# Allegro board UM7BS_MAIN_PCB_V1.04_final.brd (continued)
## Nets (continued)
LPC_AD3: CN11.5 U1.N1(MF_LPC_AD3) U31.7(LAD3/GPM3)
LPC_CLK_EC: CN11.10 R85.1 R87.1 U31.13(LPCCLK/GPM4)
LPC_CLKRUN#: R411.2 U1.T3(LPC_CLKRUNB)
LPC_FRAME#: CN11.9 U1.P3(LPC_FRAMEB) U31.6(LFRAME#/GPM5)
LPC_SERIRQ: R390.1 U1.T2(ILB_SERIRQ) U29.3(A) U30.2(A1)
LPC_SERIRQ_EC: CN11.12 R390.2 U29.4(B) U30.10(B1) U31.5(SERIRQ/GPM6)
LPCPD#: R440.2 R441.1 U31.17(LPCPD#/GPE6) U32.7(B4)
LX3: L6.2 U11.10(LX3)
LX4: L7.2 R840.2 U11.25(LX4)
LX5: L8.2 R841.2 U11.20(LX5)
M_A_A0: CN1.98(A0) U1.BB47(DDR3_M0_MA_0)
M_A_A1: CN1.97(A1) U1.BC42(DDR3_M0_MA_1)
M_A_A2: CN1.96(A2) U1.BJ48(DDR3_M0_MA_2)
M_A_A3: CN1.95(A3) U1.BH47(DDR3_M0_MA_3)
M_A_A4: CN1.92(A4) U1.BD42(DDR3_M0_MA_4)
M_A_A5: CN1.91(A5) U1.BH48(DDR3_M0_MA_5)
M_A_A6: CN1.90(A6) U1.BB46(DDR3_M0_MA_6)
M_A_A7: CN1.86(A7) U1.BE46(DDR3_M0_MA_7)
M_A_A8: CN1.89(A8) U1.BD44(DDR3_M0_MA_8)
M_A_A9: CN1.85(A9) U1.BE52(DDR3_M0_MA_9)
M_A_A10: CN1.107(A10/AP) U1.BJ45(DDR3_M0_MA_10)
M_A_A11: CN1.84(A11) U1.BB49(DDR3_M0_MA_11)
M_A_A12: CN1.83(A12/BC#) U1.BF48(DDR3_M0_MA_12)
M_A_A13: CN1.119(A13) U1.BF44(DDR3_M0_MA_13)
M_A_A14: CN1.80(A14) U1.BD47(DDR3_M0_MA_14)
M_A_A15: CN1.78(A15) U1.BD49(DDR3_M0_MA_15)
M_A_BS0: CN1.109(BA0) U1.BH46(DDR3_M0_BS_0)
M_A_BS1: CN1.108(BA1) U1.AY40(DDR3_M0_BS_1)
M_A_BS2: CN1.79(BA2) U1.BF52(DDR3_M0_BS_2)
M_A_CAS#: CN1.115(CAS#) U1.BG45(DDR3_M0_CASB)
M_A_DM0: CN1.11(DM0) U1.AP52(DDR3_M0_DM_0)
M_A_DM1: CN1.28(DM1) U1.AT48(DDR3_M0_DM_1)
M_A_DM2: CN1.46(DM2) U1.AP44(DDR3_M0_DM_2)
M_A_DM3: CN1.63(DM3) U1.BA53(DDR3_M0_DM_3)
M_A_DM4: CN1.136(DM4) U1.BG41(DDR3_M0_DM_4)
M_A_DM5: CN1.153(DM5) U1.AY36(DDR3_M0_DM_5)
M_A_DM6: CN1.170(DM6) U1.BD32(DDR3_M0_DM_6)
M_A_DM7: CN1.187(DM7) U1.BH30(DDR3_M0_DM_7)
M_A_DQ0: CN1.4(DQ4) U1.AK51(DDR3_M0_DQ_0)
M_A_DQ1: CN1.5(DQ0) U1.AL51(DDR3_M0_DQ_1)
M_A_DQ2: CN1.15(DQ2) U1.AT52(DDR3_M0_DQ_2)
M_A_DQ3: CN1.17(DQ3) U1.AR51(DDR3_M0_DQ_3)
M_A_DQ4: CN1.7(DQ1) U1.AL53(DDR3_M0_DQ_4)
M_A_DQ5: CN1.6(DQ5) U1.AK52(DDR3_M0_DQ_5)
M_A_DQ6: CN1.16(DQ6) U1.AR53(DDR3_M0_DQ_6)
M_A_DQ7: CN1.18(DQ7) U1.AP51(DDR3_M0_DQ_7)
M_A_DQ8: CN1.22(DQ12) U1.AP48(DDR3_M0_DQ_8)
M_A_DQ9: CN1.23(DQ9) U1.AT47(DDR3_M0_DQ_9)
M_A_DQ10: CN1.33(DQ10) U1.AY48(DDR3_M0_DQ_10)
M_A_DQ11: CN1.34(DQ14) U1.AV50(DDR3_M0_DQ_11)
M_A_DQ12: CN1.24(DQ13) U1.AP47(DDR3_M0_DQ_12)
M_A_DQ13: CN1.21(DQ8) U1.AT50(DDR3_M0_DQ_13)
M_A_DQ14: CN1.35(DQ11) U1.AY50(DDR3_M0_DQ_14)
M_A_DQ15: CN1.36(DQ15) U1.AV45(DDR3_M0_DQ_15)
M_A_DQ16: CN1.42(DQ21) U1.AT40(DDR3_M0_DQ_16)
M_A_DQ17: CN1.41(DQ17) U1.AP42(DDR3_M0_DQ_17)
M_A_DQ18: CN1.51(DQ18) U1.AT38(DDR3_M0_DQ_18)
M_A_DQ19: CN1.40(DQ20) U1.AP40(DDR3_M0_DQ_19)
M_A_DQ20: CN1.50(DQ22) U1.AT44(DDR3_M0_DQ_20)
M_A_DQ21: CN1.52(DQ23) U1.AV41(DDR3_M0_DQ_21)
M_A_DQ22: CN1.39(DQ16) U1.AP41(DDR3_M0_DQ_22)
M_A_DQ23: CN1.53(DQ19) U1.AV42(DDR3_M0_DQ_23)
M_A_DQ24: CN1.67(DQ26) U1.BD52(DDR3_M0_DQ_24)
M_A_DQ25: CN1.58(DQ29) U1.AV52(DDR3_M0_DQ_25)
M_A_DQ26: CN1.69(DQ27) U1.BC53(DDR3_M0_DQ_26)
M_A_DQ27: CN1.56(DQ28) U1.AV51(DDR3_M0_DQ_27)
M_A_DQ28: CN1.57(DQ24) U1.AW51(DDR3_M0_DQ_28)
M_A_DQ29: CN1.70(DQ31) U1.BC52(DDR3_M0_DQ_29)
M_A_DQ30: CN1.59(DQ25) U1.AW53(DDR3_M0_DQ_30)
M_A_DQ31: CN1.68(DQ30) U1.BB51(DDR3_M0_DQ_31)
M_A_DQ32: CN1.129(DQ32) U1.BG42(DDR3_M0_DQ_32)
M_A_DQ33: CN1.132(DQ37) U1.BG43(DDR3_M0_DQ_33)
M_A_DQ34: CN1.141(DQ34) U1.BG37(DDR3_M0_DQ_34)
M_A_DQ35: CN1.140(DQ38) U1.BJ37(DDR3_M0_DQ_35)
M_A_DQ36: CN1.130(DQ36) U1.BH42(DDR3_M0_DQ_36)
M_A_DQ37: CN1.131(DQ33) U1.BJ41(DDR3_M0_DQ_37)
M_A_DQ38: CN1.143(DQ35) U1.BH36(DDR3_M0_DQ_38)
M_A_DQ39: CN1.142(DQ39) U1.BH38(DDR3_M0_DQ_39)
M_A_DQ40: CN1.147(DQ40) U1.BC36(DDR3_M0_DQ_40)
M_A_DQ41: CN1.149(DQ41) U1.BA36(DDR3_M0_DQ_41)
M_A_DQ42: CN1.157(DQ42) U1.AU34(DDR3_M0_DQ_42)
M_A_DQ43: CN1.158(DQ46) U1.AU32(DDR3_M0_DQ_43)
M_A_DQ44: CN1.146(DQ44) U1.BF36(DDR3_M0_DQ_44)
M_A_DQ45: CN1.148(DQ45) U1.BD36(DDR3_M0_DQ_45)
M_A_DQ46: CN1.159(DQ43) U1.AV34(DDR3_M0_DQ_46)
M_A_DQ47: CN1.160(DQ47) U1.AV32(DDR3_M0_DQ_47)
M_A_DQ48: CN1.163(DQ48) U1.BF34(DDR3_M0_DQ_48)
M_A_DQ49: CN1.166(DQ53) U1.BC34(DDR3_M0_DQ_49)
M_A_DQ50: CN1.176(DQ55) U1.BA32(DDR3_M0_DQ_50)
M_A_DQ51: CN1.177(DQ51) U1.BD30(DDR3_M0_DQ_51)
M_A_DQ52: CN1.165(DQ49) U1.BD34(DDR3_M0_DQ_52)
M_A_DQ53: CN1.164(DQ52) U1.BA34(DDR3_M0_DQ_53)
M_A_DQ54: CN1.174(DQ54) U1.BF30(DDR3_M0_DQ_54)
M_A_DQ55: CN1.175(DQ50) U1.BD28(DDR3_M0_DQ_55)
M_A_DQ56: CN1.181(DQ56) U1.BJ33(DDR3_M0_DQ_56)
M_A_DQ57: CN1.194(DQ63) U1.BG29(DDR3_M0_DQ_57)
M_A_DQ58: CN1.180(DQ60) U1.BH34(DDR3_M0_DQ_58)
M_A_DQ59: CN1.183(DQ57) U1.BG32(DDR3_M0_DQ_59)
M_A_DQ60: CN1.193(DQ59) U1.BG28(DDR3_M0_DQ_60)
M_A_DQ61: CN1.192(DQ62) U1.BJ29(DDR3_M0_DQ_61)
M_A_DQ62: CN1.191(DQ58) U1.BH28(DDR3_M0_DQ_62)
M_A_DQ63: CN1.182(DQ61) U1.BG33(DDR3_M0_DQ_63)
M_A_DQS0: CN1.12(DQS0) U1.AM52(DDR3_M0_DQS_0)
M_A_DQS1: CN1.29(DQS1) U1.AV47(DDR3_M0_DQS_1)
M_A_DQS2: CN1.47(DQS2) U1.AT42(DDR3_M0_DQS_2)
M_A_DQS3: CN1.64(DQS3) U1.AY52(DDR3_M0_DQS_3)
M_A_DQS4: CN1.137(DQS4) U1.BH40(DDR3_M0_DQS_4)
M_A_DQS5: CN1.154(DQS5) U1.AT32(DDR3_M0_DQS_5)
M_A_DQS6: CN1.171(DQS6) U1.BC30(DDR3_M0_DQS_6)
M_A_DQS7: CN1.188(DQS7) U1.BH32(DDR3_M0_DQS_7)
M_A_DQS#0: CN1.10(DQS#0) U1.AM51(DDR3_M0_DQSB_0)
M_A_DQS#1: CN1.27(DQS#1) U1.AV48(DDR3_M0_DQSB_1)
M_A_DQS#2: CN1.45(DQS#2) U1.AT41(DDR3_M0_DQSB_2)
M_A_DQS#3: CN1.62(DQS#3) U1.BA51(DDR3_M0_DQSB_3)
M_A_DQS#4: CN1.135(DQS#4) U1.BG39(DDR3_M0_DQSB_4)
M_A_DQS#5: CN1.152(DQS#5) U1.AT34(DDR3_M0_DQSB_5)
M_A_DQS#6: CN1.169(DQS#6) U1.BC32(DDR3_M0_DQSB_6)
M_A_DQS#7: CN1.186(DQS#7) U1.BG31(DDR3_M0_DQSB_7)
M_A_RAS#: CN1.110(RAS#) U1.BA40(DDR3_M0_RASB)
M_A_WE#: CN1.113(WE#) U1.BH44(DDR3_M0_WEB)
M_CKE0: CN1.73(CKE0) U1.BB44(DDR3_M0_CKE_0)
M_CKE1: CN1.74(CKE1) U1.AY42(DDR3_M0_CKE_1)
M_CLK_DDR0: CN1.101(CK0) U1.BD40(DDR3_M0_CK_0)
M_CLK_DDR1: CN1.102(CK1) U1.BD38(DDR3_M0_CK_1)
M_CLK_DDR#0: CN1.103(CK0#) U1.BF40(DDR3_M0_CKB_0)
M_CLK_DDR#1: CN1.104(CK1#) U1.BF38(DDR3_M0_CKB_1)
M_CS#0: CN1.114(S0#) U1.AY38(DDR3_M0_CSB_0)
M_CS#1: CN1.121(S1#) U1.AU38(DDR3_M0_CSB_1)
M_ODT0: CN1.116(ODT0) U1.AV36(DDR3_M0_ODT_0)
M_ODT1: CN1.120(ODT1) U1.BA38(DDR3_M0_ODT_1)
MDI0+: U22.1(MDIP0) U23.7(TD+)
MDI0-: U22.2(MDIN0) U23.8(TD-)
MDI1+: U22.4(MDIP1) U23.1(RD+)
MDI1-: U22.5(MDIN1) U23.2(RD-)
MDI2+: U22.7(MDIP2(NC)) U24.7(TD+)
MDI2-: U22.8(MDIN2(NC)) U24.8(TD-)
MDI3+: U22.10(MDIP3(NC)) U24.1(RD+)
MDI3-: U22.11(MDIN3(NC)) U24.2(RD-)
MIC1L-VREFO: R337.2 U25.31(MIC1-VREFO-L)
MIC1R-VREFO: R335.2 U25.30(MIC1-VREFO-R)
MIC2-VREFO: R333.1 U25.29(MIC2-VREFO)
MIC_SEL_DET: J2.6 Q36.1(G) R340.1 R349.1 R404.2
MIC_SEL_SPDIF: Q36.3(D) R346.2 R450.2 U25.48(SPDIF-OUT/GPIO2)
OVPA: R366.1 R645.2 R883.2 R3096.2 U41.7(OVP)
PCIE_LAN_WAKE#: R95.2 R304.2
PCIE_RXN0_LAN: C346.1 U1.J20(PCIE_RXN0)
PCIE_RXN1_WLAN: CN26.43(PERN0) U1.F20(PCIE_RXN1)
PCIE_RXP0_LAN: C347.1 U1.G20(PCIE_RXP0)
PCIE_RXP1_WLAN: CN26.41(PERP0) U1.D20(PCIE_RXP1)
PCIE_TXN0_LAN: C4.2 U22.18(HSIN)
PCIE_TXN1_WLAN: C6.2 CN26.37(PETN0)
PCIE_TXP0_LAN: C3.2 U22.17(HSIP)
PCIE_TXP1_WLAN: C5.2 CN26.35(PETP0)
PCIE_WIFI_WAKE#: R97.2 R787.1
PD#: U25.47(PDB) U26.4(Y)
PERSTB: R306.1 U22.25(PERSTB)
PM_BATLOW#: R122.1 R447.1 R448.1 U1.C14(PMU_BATLOW_B)
PM_RSMRST#: R82.1 R393.1 R591.2 U1.F18(RSMRST_B)
PM_SLP_S0IX#: C566.2 R225.2 R442.1 U6.7(B4)
PM_SLP_S3#: C23.2 R219.1 R557.1 R3112.2 U6.9(B2) U31.70(ADC4/GPI4)
PM_SLP_S4#: C24.2 U6.8(B3) U31.69(ADC3/GPI3)
PMC_ACPRESENT: Q8.3(D) R127.2 U1.C13(PMU_AC_PRESENT)
PMC_PLTRST: R166.1 R602.2 TP15.1 U6.2(A1)
PMC_PWRBTN#: R121.2 R415.1 U1.M16(PMU_PWRBTN_B) U30.4(A3)
PMC_PWRBTN#_EC: R415.2 R416.1 U30.8(B3) U31.18(RI1#/GPD0)
PMC_RSTBTN: R118.1 R119.1 R124.2 R412.1 U1.AF2(PMU_RESETBUTTON_B) U30.3(A2)
PMC_SLP_S0IX: R206.1 R605.2 TP14.1 U6.5(A4) U11.61(SLP_S0IXB)
PMC_SLP_S3: R203.1 R604.2 TP12.1 U6.3(A2) U11.62(SLP_S3B)
PMC_SLP_S4: R603.2 TP13.1 U6.4(A3) U11.63(SLP_S4B)
PMC_SUS_STAT#: R440.1 U1.D14(SUS_STAT_B) U32.5(A4)
PMC_SUSPWRDNACK: Q43.1(G) R86.1 R429.1 U1.AE3(SUSPWRDNACK)
PMIC_EN: R187.2 R552.2 R553.2 U11.13(PMICEN)
PMU_SUSCLK: R561.1 R788.2 U1.C15(PMU_SUSCLK)
POWSW#: D22.N D23.N R499.1 SW1.1
PROCHOT#_EC: R456.2 R464.2 U31.76(TACH2/HDIO2/GPJ0) U33.2(A)
PS_LATCH#: D22.P Q45.1(G) R498.1 R500.1
PSELF: R177.2 R178.1 U9.17(PSELF)
PSMS: R800.1 U95.20(GPIO0)
PWM: R528.1 R530.2 R531.1 R534.1 U41.16(PWM)
PWR_LED_WHITE: Q16.1(IN) U31.56(KSO16/SMOSI/GPC3)
PWR_SW: C704.1 CN23.4(VDD) U95.24(PMOS)
PWRONLATCHG: C465.1 Q44.4(G) R496.1 R498.2
R_OUT+: CN12.1 R361.1
R_OUT-: CN12.2 R360.1
REGOUT: L10.1 U22.36(REGOUT)
REXT: R267.2 U16.26(REXT)
RLV_AMP: R266.2 U16.27(RLV_AMP)
RLV_CFG: R274.1 R275.2 U16.22(RLV_CFG)
RLV_LNK: R273.1 U16.21(RLV_LNK/GPIO0) U18.7(WP/WC#)
RSET: R297.1 U22.46(RSET)
RSMRST#_EC: R393.2 U31.19(L80HLAT/BAO/GPE0)
RSMRST_PWRGD: R208.1 U31.96(HSCE#/GPH3/ID3)
RSTZ: C707.1 R801.2 R802.2 U95.22(RSTZ)
RTA: R958.2 U41.8(RT)
RUNTIME_SCI#_EC: D10.P R417.2 R430.1 U30.7(B4)
SA0_DIM0: CN1.197(SA0) R147.1 R150.1
SA1_DIM0: CN1.201(SA1) R151.1 R590.1
SATA_DEVSLP0: R24.2 R560.1
SATA_LED#: R22.1 U1.AH3(SATA_LEDN)
SATA_RXN0: C263.2 U1.M28(SATA_RXN0)
SATA_RXN1: C433.1 U1.K28(SATA_RXN1)
SATA_RXP0: C171.2 U1.N28(SATA_RXP0)
SATA_RXP1: C434.1 U1.J28(SATA_RXP1)
SATA_TXN0: C296.2 U1.B30(SATA_TXN0)
SATA_TXN1: C432.1 U1.A29(SATA_TXN1)
SATA_TXP0: C312.2 U1.C31(SATA_TXP0)
SATA_TXP1: C429.1 U1.C29(SATA_TXP1)
SD_CDZ: CN23.11(CD) U95.21(SD_CDZ)
SD_CLK: CN23.5(CLK) U95.14(SD_CLK)
SD_CMD: CN23.2(CMD) U95.15(SD_CMD)
SD_D0: CN23.7(DATA0) U95.13(SB9)
SD_D1: CN23.8(DATA1) U95.12(SB8)
SD_D2: CN23.9(DATA2) U95.17(SB13)
SD_D3: CN23.1(CD/DAT3) U95.16(SB12)
SD_WP: CN23.10(WP) U95.10(SB5)
SDMMC1_RCLK: R598.1 U1.T13(MMC1_RCLK)
SECURITY_FLASH: R61.2 R63.2 U1.AH52(GPIO_SUS5)
SENSOR: R585.2 R586.2 U31.66(ADC0/GPI0)
SLPS3#_CONTROL: Q19.3(D) R215.2 R217.2
SMB_CLK_S2: CN1.202(SCL) R70.2 R310.2 R785.2 U5.6(B2)
SMB_DATA_S2: CN1.200(SDA) R69.2 R311.2 R784.2 U5.7(B1)
SMBCLK: R310.1 U22.14(SMBCLK(NC))
SMBDATA: R311.1 R313.1 U22.15(SMBDATA(NC))
SMC_ONOFF#: D23.P R400.2 R446.2
SMC_SHUTDOWN#: Q46.1(G) R395.2 R501.2
SOC_COLD_RESET_N: R454.1 U1.Y3(GPIO_ALERT)
SOC_EXTSMI#: R73.1 R74.1 R432.1 U1.AG53(GPIO_SUS7) U32.2(A1)
SOC_EXTSMI#_EC: D9.P R422.1 R432.2 U32.10(B1)
SOC_FLASHEN: R43.1 R455.1 U3.3(ON)
SOC_RUNTIME_SCI: R71.2 R417.1 U1.AG51(GPIO_SUS6) U30.5(A4)
SOC_SMB_CLK: R62.1 U1.AM6(MF_SMB_CLK) U5.3(A2)
SOC_SMB_DATA: R64.1 U1.AM7(MF_SMB_DATA) U5.2(A1)
SOC_WAKE_SCI: R52.1 R433.1 U32.3(A2)
SODIMM_VREF_CA0: C119.2 C120.2 CN1.126(VREF_CA) R153.1 R154.2
SODIMM_VREF_DQ0: C116.2 C117.2 CN1.1(VREF_DQ) R148.1 R152.2
SPI_CLK: R36.1 U2.6(CLK) U4.6(SCLK)
SPI_CS0#: R37.1 R568.1 U2.1(CS#) U4.1(CS#)
SPI_SI: R39.1 U2.5(DI(DQ0)) U4.5(SI/SIO0)
SPI_SO: R38.1 U2.2(DO(DQ1)) U4.2(SO/SIO1)
SPK_L+: R362.2 U25.42(SPK-OUT-L+)
SPK_L-: R363.2 U25.43(SPK-OUT-L-)
SPK_R+: R361.2 U25.45(SPK-OUT-R+)
SPK_R-: R360.2 U25.44(SPK-OUT-R-)
SPKR: R342.2 U1.H4(SPKR)
SSTCMP: R3093.1 U41.15(SSTCMP)
STATUS: R616.1 U41.14(STATUS)
TBCLK: R418.2 U31.85(PS2CLK0/TMB0/GPF0/CEC)
TBDATA: R419.2 U31.86(PS2DAT0/TMB1/GPF1)
TP_FUSE_LDO: TP7.1 U1.M20(RSVD2)
TP_FUSE_PWR: TP6.1 U1.K20(RSVD1)
TXN0_LVDS: C281.2 U16.5(DRX0N)
TXN1_LVDS: C290.2 U16.8(DRX1N)
TXP0_LVDS: C287.2 U16.4(DRX0P)
TXP1_LVDS: C292.1 U16.7(DRX1P)
USB3_PWRON: R475.2 R482.2 R487.2 R492.2 U31.31(PWM5/GPA5) U35.4(EN) U38.4(EN) U39.4(EN) U40.4(EN)
USB3_RX0_N: FIL6.4(GND) R471.1 U1.D28(USB3_RXN0)
USB3_RX0_P: FIL6.1(UNB) R473.1 U1.F28(USB3_RXP0)
USB3_RX1_N: FIL16.4(GND) R2983.1 U1.D30(USB3_RXN1)
USB3_RX1_P: FIL16.1(UNB) R2982.1 U1.F30(USB3_RXP1)
USB3_TX0_N: C442.2 U1.C32(USB3_TXN0)
USB3_TX0_P: C443.2 U1.B32(USB3_TXP0)
USB3_TX1_N: C2762.2 U1.C33(USB3_TXN1)
USB3_TX1_P: C2763.2 U1.A33(USB3_TXP1)
USB_OC0#: C441.1 R89.1 R472.1 R474.2 U1.P16(USB_OC1_B) U35.3(OCB)
USB_OC1#: C448.1 R88.1 R479.1 R481.2 U1.P14(USB_OC0_B) U38.3(OCB)
USB_OC2#: C453.1 C458.1 R467.1 R484.1 R486.2 R490.1 R491.2 U39.3(OCB) U40.3(OCB)
USB_PN0: FIL5.1(UNB) R469.1 U1.B42(USB_DN0)
USB_PN1: FIL15.1(UNB) R2981.1 U1.B44(USB_DN1)
USB_PN2: FIL11.2(DUMMY2) R578.2 U1.A41(USB_DN2)
USB_PN3: FIL10.1(UNB) R489.1 U1.A45(USB_DN3)
USB_PN4: FIL9.3(DUMMY3) R485.1 U1.C40(USB_DN4)
USB_PP0: FIL5.4(GND) R470.1 U1.C42(USB_DP0)
USB_PP1: FIL15.4(GND) R2980.1 U1.C43(USB_DP1)
USB_PP2: FIL11.3(DUMMY3) R577.2 U1.C41(USB_DP2)
USB_PP3: FIL10.4(GND) R488.1 U1.C45(USB_DP3)
USB_PP4: FIL9.2(DUMMY2) R483.1 U1.B40(USB_DP4)
V_DAC: C350.2 C351.2 C358.2 C359.2 U23.3(CT1) U23.6(CT2) U24.3(CT1) U24.6(CT2)
VCLK: C177.1 C178.1 U10.19(VCLK)
VFB1: R179.1 R180.2 U10.2(VFB1)
VFB2: R181.1 R183.1 U10.4(VFB2)
VGG_GND: R839.2 U11.6(PGNDSNS2)
VGG_LX: C211.2 L4.2 Q14.7(S1/D2) R580.2 U11.4(SW2)
VGG_SENSEN: R770.2 R826.1
VGG_SENSEN_R: R770.1 U1.AD22(UNCORE_VSS_SENSE2)
VGG_SENSEP: R105.1 R848.2
VGG_SENSEP_R: R848.1 U1.AD24(DDI_VGG_SENSE)
VNN_SVID_SENSEP: R109.1 R565.2
VREFA: C992.1 R616.2 U41.12(VREF)
VREG3: C156.1 D29.P R185.2 R186.1 R388.2 U10.3(VREG3)
VREG5: C175.2 U10.13(VREG5)
VSPI_KBC: C427.1 D12.N R449.1 R457.1 R460.2 R461.2 U34.8(VCC)
WAKE_SCI_EC: R433.2 R434.1 R438.1 U32.9(B2)
WIFI_3P3_RST#: Q39.3(D) R364.2 U27.1(A)
WIFI_PCIE_RST: Q40.1(G) R115.1 U1.V12(SPI1_MOSI)
WIFI_PERST#: CN26.52(PERST0*) R372.1 U27.4(Y)
WIFI_PWRON: R380.2 U28.3(EN/ENB) U31.112(RING#/PWRFAIL#/CK32KOUT/LPCRST#)
WIFI_RF_KILL_R*: CN26.56(W_DISABLE1* (O)(0/3.3V)) R193.1
WIRELESS_ON: R193.2 U31.33(GINT/CTS0#/GPD5)
WP#: R40.1 U1.U1(FST_SPI_D2) U2.3(WP#(DQ2)) U4.3(WP#/SIO2)
WRST#: C422.2 R445.1 SW2.1 SW2.3 U31.14(WRST#)
XTAL1: C324.1 U22.43(CKXTAL1) X5.1
XTAL2: C323.1 U22.44(CKXTAL2) X5.3
XTAL25M_IN: C12.2 R45.2 U1.P24(OSCIN) X1.1
XTAL25M_OUT: C13.2 R45.1 U1.M22(OSCOUT) X1.3
N46460: R1.1 U1.BA28(DDR3_M0_RCOMPPD)
N52618: R15.2 U1.G38(D\D\I\0\_\P\L\L\O\B\S\)
N52622: R15.1 U1.F38(DDI0_PLLOBS_P)
N53865: R17.2 U1.F49(D\D\I\1\_\P\L\L\O\B\S\)
N53869: R17.1 U1.F47(DDI1_PLLOBS_P)
N59327: R16.1 U1.P44(MCSI_COMP)
N59478: R20.1 U1.P13(SDMMC1_RCOMP)
N59568: R21.1 U1.P12(SDMMC3_RCOMP)
N60711: C4.1 U1.B24(PCIE_TXN0)
N60715: C3.1 U1.C24(PCIE_TXP0)
N61460: C6.1 U1.C25(PCIE_TXN1)
N61464: C5.1 U1.A25(PCIE_TXP1)
N61983: R28.1 U1.AM14(PCIE_CLKREQ3B)
N61987: R29.1 U1.AK14(PCIE_CLKREQ2B)
N62557: R35.2 U1.F26(PCIE_OBSN)
N62561: R35.1 U1.D26(PCIE_OBSP)
N64250: R25.2 U1.M30(SATA_OBSN)
N64254: R25.1 U1.N30(SATA_OBSP)
N64675: R24.1 U1.AG1(SATA_GP2)
N64950: C7.1 R30.1 U1.AF13(MF_HDA_RSTB)
N65002: R33.1 U1.AF12(MF_HDA_SYNC)
N65040: R31.1 U1.AD9(MF_HDA_CLK)
N65098: R32.1 U1.AD7(MF_HDA_SDI0)
N65529: R34.1 U1.AF14(MF_HDA_SDO)
N66939: C10.2 U3.6(CT)
N72611: R46.2 U1.P20(ICLKICOMP)
N72676: R47.2 U1.N20(ICLKRCOMP)
N73559: R44.2 U1.P26(RSVD18)
N73565: R48.2 U1.AH45(RSVD1)
N73585: R44.1 R48.1 R49.2
N73829: R50.2 U1.A9(MF_PLT_CLK0)
N73942: R51.2 R52.2 U1.AD51(GPIO_SUS0)
N74220: R53.2 R56.1 U1.AD52(GPIO_SUS1)
N74266: R54.2 R57.1 U1.AH50(GPIO_SUS2)
N74833: R55.1 U1.AH48(GPIO_SUS3)
N75113: R58.2 R59.1 U1.AH51(GPIO_SUS4)
N75766: Q5.3(D) R63.1
N77258: R60.2 U1.AH40(GPIO0_RCOMP)
N79829: R72.1 U5.5(OE)
N80354: R65.1 U1.AM9(MF_SMB_ALERTB)
N81322: R94.2 U1.F34(USB3_OBSN)
N81326: R94.1 U1.D34(USB3_OBSP)
N82446: R91.1 U1.B47(USB_VBUSSNS)
N82527: R92.1 U1.A48(USB_RCOMP)
N82633: R100.2 U1.N38(USB_HSIC_RCOMP)
N83371: R80.2 U1.M13(RSVD5)
N83609: R93.2 U1.T4(LPC_HVT_RCOMP)
N83745: R85.2 U1.P2(MF_LPC_CLKOUT0)
N83769: R87.2 U1.R3(MF_LPC_CLKOUT1)
N86700: C20.2 R81.1 U1.K18(BRTCX2_PAD) X2.4 X3.2
N86712: C16.2 R81.2 U1.M18(BRTCX1_PAD) X2.1 X3.1
N87028: C17.2 U1.F16(BVCCRTC_EXTPAD)
N87161: C19.1 R79.1 U1.D18(SRTCRST_B)
N88012: C18.1 R83.1 U1.J16(RTEST_B)
N88403: R84.1 U1.G18(RSVD_VSS)
N89664: Q53.2(S) R90.1 U1.N16(PMU_WAKE_B)
N89704: TP5.1 U1.B12(PMU_SLP_LAN_B)
N89904: R111.1 U1.AD40(SVID0_ALERT_B)
N912733: R129.1 U1.AA30(RSVD1)
N926610: C105.1 R133.1 R134.1 U1.G1(SDIO_V3P3A_V1P8A_G33)
N936455: R135.1 U1.A3(RSVD_VSS)
N964422: LED1.1(P) U7.4(Y)
N967359: LED1.2(N) R145.2
N1003987: CN1.198(EVENT#) R146.2 R149.2
N1049332: Q35.3(D) R308.2 U22.16(CLKREQB)
N1051586: C334.2 R296.1 U21.4(SS)
N1052520: CN6.7(P7) FIL4.3(DUMMY3) R320.2
N1052530: CN6.5(P5) FIL3.3(DUMMY3) R319.2
N1052610: CN6.6(P6) FIL2.2(DUMMY2) R316.2
N1052618: CN6.1(P1) FIL1.3(DUMMY3) R312.2
N1052644: CN6.2(P2) FIL1.2(DUMMY2) R314.2
N1052708: CN6.3(P3) FIL2.3(DUMMY3) R315.2
N1052848: CN6.4(P4) FIL3.2(DUMMY2) R318.2
N1052868: CN6.8(P8) FIL4.2(DUMMY2) R326.2
N1061129: R331.2 U25.33(HPOUT-R(PORT-I-R))
N1061133: R332.2 U25.32(HPOUT-L(PORT-I-L))
N1061141: C364.1 U25.34(CPVEE)
N1061235: C386.1 C387.2 FB13.2 U25.1(DVDD)
N1062073: R339.2 R340.2 U25.13(SENSE A)
N1062173: C378.2 U25.20(MIC1-R(PORT-B-R))
N1062273: C379.2 U25.19(MIC1-L(PORT-B-L))
N1062851: Q37.3(D) R351.2 R358.2 U26.2(B)
N1062939: Q38.1(G) R359.1
N1063057: Q37.1(G) Q38.3(D) R353.2
N1063545: C384.2 U25.12(PCBEEP)
N1063553: C384.1 R341.2 R342.1
N1064125: C385.2 U25.7(LDO3-CAP)
N1064657: R338.1 U25.15(JDREF)
N1064691: C375.1 U25.37(CBP)
N1064695: C375.2 U25.35(CBN)
N1064865: C366.1 U25.27(LDO1-CAP)
N1091368: Q46.3(D) R500.2
N1091486: Q45.3(D) R497.1
N1121703: C425.1 R459.1 U31.2(CK32KE/GPJ7) X6.4 X7.2
N1122397: C423.1 R458.2 R459.2 U31.128(CK32K/GPJ6) X6.1 X7.1
N1123071: R411.1 U31.93(CLKRUN#/GPH0/ID0)
N1123827: C424.1 U31.12(VCORE)
N1123831: Q42.1(G) Q43.3(D) R413.2
N1124299: R450.1 U31.109(TXD/SOUT0/GPB1)
N1124955: R442.2 U31.124(TMRI1/GPC6)
N1125039: R386.2 U29.5(OE)
N1125207: R397.1 U31.84(EGCLK/GPE3)
N1125735: R449.2 U31.106(GPG0/FSCE1#/SSCE1#)
N1125963: R428.1 U31.22(LPCRST#/GPD2)
N1126063: D8.N R409.1 R410.1 U31.11(VCC)
N1126133: R400.1 R403.1 U31.107(DTR1#/SBUSY/GPG1/ID7/FDIO2)
N1126239: D10.N R430.2 U31.23(ECSCI#/GPD3)
N1126307: R444.1 R446.1 U31.125(PWRSW/GPE4)
N1126437: D11.N R431.2 U31.4(KBRST#/GPB6)
N1126855: R462.1 U31.113(VSS5)
N1127021: R463.1 U31.122(VSS6)
N1127039: R439.1 U31.48(TACH1A/TMA1/GPD7)
N1127083: R455.2 U31.77(HDIO3/GPJ1)
N1127147: R461.1 U34.3(WP#/ACC)
N1127169: R460.1 U34.7(HOLD#)
N1127267: R435.2 U31.47(TACH0A/GPD6)
N1127313: R438.2 U31.16(PWUREQ#/GPC7/BBO)
N1127321: D9.N R422.2 U31.15(ECSMI#/GPD4)
N1127467: R395.1 U31.82(EGAD/GPE1)
N1127901: R391.2 U30.12(OE)
N1128819: R427.2 U32.12(OE)
N1129433: R398.1 U31.99(HMOSI/GPH6/ID6)
N1129705: R447.2 U31.21(RI2#/GPD1)
N1129743: R404.1 U31.98(HMISO/GPH5/ID5)
N5550068: R157.2 U8.H5(DAT2)
N5550072: R165.2 R576.2 U8.W5(CMD)
N5550076: R167.2 U8.W6(CLK)
N5550080: R164.2 U8.H4(DAT1)
N5550084: R162.2 U8.J2(DAT3)
N5550116: R159.2 U8.J5(DAT6)
N5550120: R158.2 U8.H3(DAT0)
N5550124: R168.2 R169.2 U8.U5(R\S\T\)
N5550128: R156.2 U8.J6(DAT7)
N5550132: R161.2 U8.J4(DAT5)
N5550136: R160.2 U8.J3(DAT4)
N5560544: R125.2 U6.12(OE)
N5591752: R195.2 R196.1 U11.60(DDR_SEL)
N5595026: R203.2 R206.2 U11.14(DDRVTTCTRL)
N5595322: C183.2 R194.2 U11.55(VSYS)
N5595880: C187.1 U11.53(VREF)
N5599060: Q52.3(D) R207.1 U11.15(IRQB)
N5599220: R208.2 R558.1 U11.16(RSMRSTB)
N5599311: R589.2 U11.27(COREPWROK)
N5599330: R210.2 U11.26(DRAMPWROK)
N5599357: R588.2 U11.28(VCCAPWROK)
N5601032: C223.2 U11.35(BOOT1)
N5603445: R211.1 U11.30(ILM1)
N5604033: C211.1 U11.5(BOOT2)
N5614603: C165.1 U10.17(VBST1)
N5614763: R182.2 U10.1(CS1)
N5615595: R184.1 U10.5(CS2)
N5615857: C166.2 U10.9(VBST2)
N5617013: R198.2 U11.64(ILIM2)
N5627138: C213.2 U11.41(BOOT6)
N5627940: R200.1 U11.45(ILM6)
N6484561: R454.2 U31.73(ADC7/CTS1/GPI7)
N6547424: R259.2 R260.2 U16.45(PWMI)
N6549298: R269.1 U17.7(WP/WC#)
N6549760: R268.1 U16.20(TESTMODE)
N6550170: L9.2 U16.15(SW_OUT) U16.16(SW_OUT-1)
N6556930: C433.2 CN3.S5
N6556942: C429.2 CN3.S2
N6556946: C432.2 CN3.S3
N6556996: C434.2 CN3.S6
N6563019: D14.N FIL5.3(DUMMY3) J4.3(D_PLUS) R470.2
N6563079: FIL7.2(DUMMY2) J4.9(STDA_SSTX+) R477.2 U37.2(D-)
N6563083: FIL7.3(DUMMY3) J4.8(STDA_SSTX-) R476.2 U37.1(D+)
N6563115: D13.N FIL5.2(DUMMY2) J4.2(D_MINUS) R469.2
N6563127: FIL6.3(DUMMY3) J4.5(STDA_SSRX-) R471.2 U36.1(D+)
N6564657: C442.1 FIL7.4(GND) R476.1
N6564689: FIL6.2(DUMMY2) J4.6(STDA_SSRX+) R473.2 U36.2(D-)
N6564811: CN20.3(D_PLUS) D20.N FIL10.3(DUMMY3) R488.2
N6564823: CN20.2(D_MINUS) D19.N FIL10.2(DUMMY2) R489.2
N6564845: C443.1 FIL7.1(UNB) R477.1
N6565949: CN19.2(D_MINUS) D17.N FIL9.4(GND) R485.2
N6565995: CN19.3(D_PLUS) D18.N FIL9.1(UNB) R483.2
N6570497: Q50.1(G) Q51.3(D) R540.2
N6570755: Q48.1(G) Q49.3(D) R537.2
N6595992: R552.1 U31.57(KSO17/SMISO/GPC5)
N6596046: R187.1 R188.2 U10.7(PGOOD)
N6633155: C394.1 J2.4 R347.1
N6633185: C393.1 J2.3 R348.1
N6635302: C399.1 J3.3 R352.1
N6635336: C398.1 J3.4 R354.1
N6638078: C378.1 R334.1
N6638082: C379.1 R336.1
N6697991: C288.1 R246.2 R247.1 R249.2 U15.5(VIN)
N6698007: C286.2 R249.1 U15.4(SS)
N6698131: Q30.3(D) R251.2 R255.1 U15.3(EN/ENB)
N6698734: Q30.1(G) Q31.3(D) R253.2
N6729809: C178.2 D5.3(D3)
N6729821: C181.1 D4.2(X2) D5.1(X1)
N6730049: C177.2 D4.3(D3)
N6738242: C256.2 Q18.4(G) R217.1
N6738428: C260.2 Q21.4(G) R222.1
N6738432: Q19.1(G) Q20.3(D) R216.2 R218.2
N6738496: Q20.1(G) R219.2
N6739070: Q22.1(G) Q23.3(D) R221.2 R224.2
N6739082: Q22.3(D) R220.2 R222.2
N6739106: Q23.1(G) R223.2
N6774197: CN24.1(1+) R551.2
N6774217: D26.P R551.1
N6835729: C461.2 R493.1
N6835771: CN21.D R494.1
N6920056: C268.2 R554.1 U44.4(SS)
N6920082: R234.2 R559.1 U44.3(EN/ENB)
N6950609: R555.2 R556.1 U46.5(SET)
N6950647: R557.2 U46.1(S\\\H\\\D\\\N\\\)
N7015906: TP10.1 U1.AF3(SATA_GP3)
N7019072: Q53.3(D) R95.1 R97.1 R592.1
N7027378: R562.1 U31.20(L80LLAT/GPE7)
N7088826: R565.1 U1.AC27(UNCORE_VSS_SENSE1)
N7139654: Q6.3(D) R113.1
N7139690: Q7.3(D) R123.1
N7139951: R567.2 U1.U51(HV_DDI2_HPD)
N7142786: R37.2 U1.V4(FST_SPI_CS0_B)
N7142796: R38.2 U1.V3(FST_SPI_D1)
N7142806: R39.2 U1.V2(FST_SPI_D0)
N7142816: R36.2 U1.W3(FST_SPI_CLK)
N7143552: R569.2 U1.V13(SPI1_MISO)
N7143994: TP11.1 U1.Y13(SPI1_CS0_B)
N7144188: R570.1 R573.1 U1.AF6(I2C1_SCL)
N7144196: R571.1 R572.1 U1.AH6(I2C1_SDA)
N7256343: C560.2 R579.1
N7380328: D28.N Q1.1(IN)
N7380332: C2.1 R3.1
N7537612: R593.1 U1.BA26(DDR3_M1_RCOMPPD)
N7539259: R594.2 U1.B52(VSS5)
N7546529: R595.2 U1.BH52(VSS15)
N7553859: R599.1 U8.H6(RFU1)
N7556393: R605.1 U1.A13(PMU_SLP_S0IX_B)
N7556465: R603.1 U1.C12(PMU_SLP_S4_B)
N7556469: R604.1 U1.B14(PMU_SLP_S3_B)
N7556492: R602.1 U1.F14(PMU_PLTRST_B)
N7642832: C691.1 R840.1
N7643520: C822.1 R841.1
N7679816: R598.2 U8.R5(RFU11)
N7679820: R597.2 U8.T5(RFU12)
N16712559: C412.2 R375.1 U28.4(SS)
N16712977: CN26.58(I2C DATA (IO)(0/3.3)) R784.1
N16713003: CN26.60(I2C CLK (O)(0/3.3)) R785.1
N16713393: CN26.50(SSCLK) R788.1
N16713507: CN26.55(PEWAKE0*) R787.2
N16714785: Q39.1(G) Q40.3(D) R365.2
N16872587: R828.1 U31.100(SSCE0#/GPG2)
N16888466: CN18.2(D_MINUS) D2513.N FIL15.2(DUMMY2) R2981.2
N16888468: CN18.5(STDA_SSRX-) FIL16.3(DUMMY3) R2983.2 U2523.1(D+)
N16888488: C2762.1 FIL14.4(GND) R2978.1
N16888504: CN18.6(STDA_SSRX+) FIL16.2(DUMMY2) R2982.2 U2523.2(D-)
N16888506: CN18.9(STDA_SSTX+) FIL14.2(DUMMY2) R2979.2 U2524.2(D-)
N16888527: C2763.1 FIL14.1(UNB) R2979.1
N16888529: CN18.3(D_PLUS) D2512.N FIL15.3(DUMMY3) R2980.2
N16888618: CN18.8(STDA_SSTX-) FIL14.3(DUMMY3) R2978.2 U2524.1(D+)
N16952168: CN9.38(DEVSLP (O)) R560.2
N16952170: CN9.68(SUSCLK(32KHZ) (O)(0/3.3V)) R561.2
N16952426: C296.1 CN9.47(PETN0/SATA-A-)
N16952428: C171.1 CN9.41(PERN0/SATA-B+)
N16952430: C312.1 CN9.49(PETP0/SATA-A+)
N16952432: C263.1 CN9.43(PERP0/SATA-B-)
N16952456: CN9.69(PEDET (NC-PCIE/GND-SATA)) R564.1
N16968122: Q95.2(S) R495.2 R663.2 R707.2 R3091.1 R3100.2
N16968198: Q95.1(G) R606.2
N16968245: D38.P D42.P L32.2 Q95.3(D) R291.2
N16969285: J5.5 R367.1
N16969287: J5.6 R3097.1
N16970384: CN40.1 R681.2 R3098.1
N16970389: CN40.3 R465.1 R636.2
N16970394: CN40.5 R466.1 R756.2
N16970402: CN40.7 R755.1 R3099.1
N16987716: Q16.3(OUT) R509.2
N16987732: LED2.2(N) R509.1
N17079846: CN3.P7 R748.2
N17211775: R467.2 U31.67(ADC1/GPI1)
N17285117: F8.1 FB16.2 FB17.2
N17343515: R170.2 U9.4(RREF)
N17343556: FIL11.1(UNB) R578.1 U9.25(DM0)
N17343558: FIL11.4(GND) R577.1 U9.26(DP0)
N17343560: R175.2 U9.14(TEST/SCL)
N17343567: FB2.2 U9.16(DVDD)
N17343572: R173.1 U9.18(PGANG)
N17343574: U9.19(OVCUR2#)
N17343576: U9.21(OVCUR1#)
N17343578: R171.1 U9.23(V5)
N17343639: U9.11(DM4)
N17343648: U9.8(DM3)
N17343650: U9.12(DP4)
N17343667: U9.9(DP3)
N17555300: R3106.1 R3107.2 U53.4(FB)
N17555409: R3108.1 U53.6(ENB)
N17556891: R746.1 R3113.2 U2525.4(FB)
N17556904: R3109.2 U2525.5(POK)
N17556998: R3112.1 U2525.6(ENB)
N17585502: C2838.1 R291.1
N72573691: C561.2 R580.1
N72594291: C562.2 R581.1
N169681891: C727.2 R3093.2

Pads without a net: CN1 77 122 125; CN3 P1 P2 P3 P11 P13 P14 P15; CN9 5 6 7 8 10 11 13 17 19 20 22 23 24 25 26 28 29 30 31 32 34 35 36 37 40 42 44 46 48 50 52 53 54 55 56 58 67; CN11 11 13 20; CN26 6 8 9 10 11 12 13 14 15 16 17 19 20 21 22 25 26 27 28 30 31 32 34 38 40 42 44 46 48 59 61 62 64 65 66 67 68 70 71 73; CN35 16 17 18; MARK1 1; MARK2 1; MARK3 1; MARK4 1; MARK5 1; MARK6 1; MARK7 1; MARK8 1; R50 1; R268 2; U1 A17 A27 A35 A37 A49 A51 A52 AA1 AA3 AA51 AB2 AB3 AB7 AB9 AB40 AB41 AB44 AB45 AB48 AB51 AB52 AC1 AC3 AC53 AD2 AD3 AD6 AD10 AD12 AD13 AD14 AD41 AD42 AD45 AD47 AD48 AE4 AF7 AF9 AF40 AF41 AF42 AF44 AF45 AF48 AF50 AG3 AH2 AH7 AK2 AK3 AK6 AK9 AK10 AK12 AK13 AK41 AK42 AK48 AL1 AL3 AM2 AM3 AM40 AM41 AM44 AM45 AM47 AM48 AP2 AP3 AP6 AP7 AP10 AP12 AP13 AP14 AR1 AR3 AT2 AT4 AT6 AT7 AT10 AT12 AT13 AT14 AT16 AT20 AT22 AT24 AT26 AT28 AT30 AU16 AU20 AU22 AU24 AU26 AU28 AU30 AV2 AV3 AV4 AV6 AV7 AV9 AV12 AV13 AV18 AV20 AV22 AW1 AW3 AY2 AY4 AY6 AY12 AY14 AY16 AY18 B4 B5 B7 B8 B10 B16 B18 B26 B34 B38 B46 B48 B49 B50 B53 BA1 BA3 BA12 BA14 BA16 BA18 BA20 BA22 BB3 BB5 BB7 BB8 BB10 BC1 BC2 BC12 BC18 BC20 BC22 BC24 BD2 BD5 BD7 BD10 BD12 BD14 BD16 BD18 BD20 BD22 BD24 BD26 BE2 BE8 BF2 BF6 BF10 BF14 BF16 BF18 BF20 BF24 BG9 BG11 BG12 BG13 BG15 BG17 BG21 BG22 BG23 BG25 BG26 BH6 BH7 BH8 BH10 BH12 BH14 BH16 BH18 BH20 BH22 BH24 BH26 BJ6 BJ9 BJ13 BJ17 BJ21 BJ25 C7 C9 C11 C16 C17 C18 C26 C27 C34 C35 C37 C38 C49 C51 C53 D2 D6 D12 D22 D36 D44 D48 D50 D52 E8 E52 E53 F2 F7 F10 F12 F22 F36 F40 F42 F44 F52 F53 G2 G24 G32 G34 G36 G40 G42 G44 G52 G53 H3 H5 H7 H46 H47 H49 H50 J1 J3 J12 J14 J24 J26 J32 J34 J36 J40 K2 K3 K6 K7 K9 K10 K26 K38 K40 K44 K47 K48 L3 L13 L51 L53 M10 M12 M26 M32 M34 M36 M38 M44 M47 M48 M51 M52 N26 N34 N36 P18 P28 P30 P34 P45 P47 P48 P50 T41 T42 T44 T45 T48 T50 V6 V7 V9 V10 V14 V45 V47 V48 V50 V51 V52 W53 Y2 Y6 Y7 Y12 Y41 Y47 Y48 Y51 Y52; U8 A4 A6 A9 A11 AA1 AA2 AA7 AA8 AA9 AA10 AA11 AA12 AA13 AA14 AE1 AE14 AG2 AG13 AH4 AH6 AH9 AH11 B2 B13 D1 D14 H1 H2 H7 H8 H9 H10 H11 H12 H13 H14 J1 J7 J8 J9 J10 J11 J12 J13 J14 K1 K3 K5 K7 K8 K9 K10 K11 K12 K13 K14 L1 L2 L3 L4 L12 L13 L14 M1 M2 M3 M5 M8 M9 M10 M12 M13 M14 N1 N2 N3 N10 N12 N13 N14 P1 P2 P3 P10 P12 P13 P14 R1 R2 R3 R12 R13 R14 T1 T2 T3 T12 T13 T14 U1 U2 U3 U6 U7 U10 U12 U13 U14 V1 V2 V3 V12 V13 V14 W1 W2 W3 W7 W8 W9 W10 W11 W12 W13 W14 Y1 Y3 Y6 Y7 Y8 Y9 Y10 Y11 Y12 Y13 Y14; U9 20 22; U16 55 56; U22 40; U23 4 5 12 13; U24 4 5 12 13; U25 14 16 21 22 23 24; U31 32 36 37 38 39 40 41 42 43 44 45 46 51 52 53 54 55 58 59 60 61 62 63 64 65 72 78 79 80 81 83 87 88 89 90 108 119 120 123; U33 1; U95 5 6 7 8 9 11

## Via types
v1: diameter 0.45, hole 0.25, TOP to BOTTOM, 2506 vias
v2: diameter 0.7, hole 0.4, TOP to BOTTOM, 917 vias

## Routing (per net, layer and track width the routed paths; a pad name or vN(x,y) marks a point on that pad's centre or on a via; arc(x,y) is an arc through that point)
3.3V_IN: length 28.5
  TOP w0.305: FB2.1 167.96,94.59 167.62,94.25 167.62,92.09 168.04,91.67 R173.2 v1(168.73,91.1)
  TOP w0.381: 179.88,96.28 R175.1 ; U9.24 v1(170.67,88.78)
  TOP w0.508: FB1.2 C149.2 ; C149.2 182.92,97.74 R172.1 ; C149.2 182.87,96.61 180.21,96.61 179.88,96.28 169.17,96.28 168.45,95.56 FB2.1
  BOTTOM w0.305: v1(170.67,88.78) 168.73,90.72 v1(168.73,91.1)
+V1.2A:
  vias: v2(164.65,26.12)
+V1.05A: length 74.6
  TOP w0.203: v1(177.44,57.72) 177.44,57.92 U1.N18
  TOP w0.254: U1.V29 179.75,62.98 v1(179.75,62.96) ; U1.U19 179.37,58.82 v1(179.75,58.44) ; v1(181.31,65.26) 181.69,64.88 U1.AA32
  LAY4 w0.203: v1(158.98,50.87) 159.26,51.16 163.87,51.16 165.99,49.04 168.19,49.04
  BOTTOM w0.203: v1(158.98,50.87) 158.98,50.87 158.98,46.36 152.58,39.96 150.81,39.96 144.93,34.08 144.93,24.43 146.06,23.3 146.06,17.19 146.54,16.71 R843.1
  BOTTOM w0.254: v1(181.75,72.71) 182.11,72.36 R111.2
  BOTTOM w0.305: v1(179.75,58.44) 179.14,59.04 C71.2 179.75,59.74 v1(179.75,59.95) ; C46.2 180.27,59.95 v1(179.75,59.95) ; v1(179.75,60.71) v1(179.75,59.95) ; v1(175.15,54.8) 175.06,54.71 C45.2 ; C58.2 174.1,54.39 v1(174.52,54.8) ; v1(177.44,57.72) 176.9,58.26 C72.2
  BOTTOM w0.381: v1(186.8,59.93) 186.84,59.93 187.65,59.12 188.14,59.12 C42.2 ; C106.2 181.18,66.15 v1(181.31,66.02) v1(181.31,66.78) 181.91,67.38 C57.2 ; v1(179.75,58.44) v1(180.53,58.44) 180.48,58.39 C53.2 ; C47.2 182.14,65.22 v1(182.1,65.26) ; C44.2 186.85,65.98 v1(186.8,66.02) ; C70.2 187.76,65.43 v1(187.59,65.26) ; C68.2 C56.2 179.05,63.65 v1(179.75,62.96) ; C43.2 187.79,59.76 v1(187.59,59.95) 188.28,60.64 C48.2
  vias: v1(160.15,28.9) v1(160.62,28.89) v1(164.95,13.21) v1(164.96,12.45) v1(168.98,45.54) v1(168.97,44.71) v1(169.61,47.62) v1(179.75,62.23) v2(160.34,29.47) v2(160.34,28.3) v2(164.49,12.83) v2(164.52,12.02) v2(169.11,48.71) v2(169.12,47.98)
+V1.5S: length 201.5
  LAY3 w0.305: v1(144.93,41.71) 144.93,44.24 146.09,45.41 150.87,45.41 151.16,45.71 155.69,45.71 159.05,49.07 166.25,49.07 170.01,45.31 170.01,43.38 173.33,40.06 173.33,38.6 176.19,35.74 183.59,35.74 184.23,36.38 184.23,37.42 185.13,38.32 185.13,44.28 185.54,44.69 v1(185.68,44.69)
  LAY4 w0.508: v1(90.14,42.88) 71.56,42.88 68.04,46.4 46.76,46.4 45.21,44.84 31.16,44.84 30.69,44.38 25.31,44.38 v1(24.95,44.74)
  BOTTOM w0.381: v1(24.95,44.74) C362.2 R330.2 ; R137.1 v1(185.68,44.69)
  BOTTOM w0.508: v1(144.93,41.71) 144.93,41.26 144.65,40.98 138.93,40.98 137.66,42.25 137.66,47.04 133.46,51.23 112.74,51.23 109.88,54.09 107.92,54.09 107.19,53.36 107.19,48.85 105.98,47.63 96.06,47.63 91.3,42.88 v1(90.14,42.88)
+V1.5S_AUDIO: length 21.9
  LAY3 w0.508: v1(33.05,31.59) 31.85,32.79 27.6,32.79 26.44,33.94 24.85,33.94 24.15,34.63 24.15,36.51 22.85,37.82 22.85,41.71 23.62,42.48 v1(24.08,42.48)
  BOTTOM w0.381: FB11.2 23,43 R330.1 24.08,42.99 v1(24.08,42.48)
  BOTTOM w0.508: v1(33.05,31.59) 32.77,31.31 R344.2
+V1.8A: length 411.5
  TOP w0.178: U11.50 163.64,26.5 164.02,26.89 v1(164.21,26.89) ; v1(156.72,16.98) 157.23,17.49 158.12,17.49 158.44,17.81 U11.18
  TOP w0.203: v1(186.58,44.64) 186.58,44.64 186.58,45.61 186.26,45.93 R119.2 ; R228.2 186.82,89.67 186.47,89.31 R229.2 186.08,88.7 185.95,88.57 185.95,86.56 v1(185.95,86.55)
  TOP w0.254: U1.Y18 180.94,58.06 v1(181.31,58.44) ; v1(181.31,63.75) 181.69,63.37 U1.AA29 ; U1.AF33 184.04,65.64 v1(183.66,66.02) U1.AD33 ; U1.AK19 186.43,58.82 v1(186.8,58.44) 186.43,58.06 U1.AK18 ; v1(179.75,57.68) 179.37,57.3 U1.U16
  TOP w0.305: v1(74.89,74.5) 73.99,74.5 73.61,74.88 53.72,74.88 v1(52.86,75.74) ; v1(170.19,49.52) 170.19,49.63 169.6,50.23 169.6,51.45 v1(168.68,52.37) ; 177.82,84.19 178.42,84.79 181.06,84.79 181.56,84.29 R67.2 181.81,84.29 182.15,84.63 182.15,85.58 182.46,85.88 R68.2
  TOP w0.381: R43.2 152.16,48.56 153.11,47.61 C9.2 ; v1(158.68,29.17) 158.33,29.52 R196.2 ; v1(74.32,68.72) 73.41,67.82 67.18,67.82 v1(66.75,68.25) ; R68.2 R73.2 R71.1 R61.1 R58.1 v1(185.95,86.55) ; C234.2 v1(156.72,16.98) ; 153.44,14.07 152.78,14.73 152.78,14.74 151.26,14.74 151,14.48 149.98,14.48 149.6,14.86 Q52.1 ; R66.1 R51.1 178.38,82.45 R53.1 178.37,83.63 177.82,84.19 177.4,84.19 176.73,83.52 R18.2 175.13,82.89 v1(175.04,82.98) ; R122.2 167.38,57.15 v1(167.34,57.11) ; R163.1 187.08,31.38 v1(186.92,31.54)
  TOP w0.406: v1(188.24,87.52) 187.99,87.52 186.35,85.88 R58.1
  TOP w0.508: v1(80.25,62.8) 78.73,61.28 v1(78.73,61.02) 78.43,60.72 76.18,60.72 v1(76.05,60.85)
  LAY3 w0.203: v1(185,37.06) 185,37.27 185.81,38.08 185.81,43.08 186.89,44.16 186.89,44.16
  LAY3 w0.305: 155.71,16.24 156.45,16.98 v1(156.72,16.98) ; 183.33,69.57 183.08,69.57 182.23,70.41 182.23,74.12 183.05,74.94 183.05,77.48 189.42,83.85 189.42,87.22 189.12,87.52 v1(188.24,87.52) ; v1(165.99,30.51) 165.99,30.49 164.21,28.71 v1(164.21,26.89)
  LAY4 w0.305: v1(167.34,57.11) 167.56,56.89 167.56,55.53 166.26,54.23 166.26,53.39 166.83,52.83 168.45,52.83 168.68,52.6 v1(168.68,52.37)
  LAY4 w0.508: v1(112.04,49.23) 109.49,51.79 105.99,51.79 94.98,62.8 v1(80.25,62.8)
  BOTTOM w0.203: v1(168.68,52.37) 168.85,52.55 R90.2 R88.2 ; 152.17,43.3 150.36,41.49 150.36,40.23 144.32,34.19 144.32,24.41 145.66,23.08 145.66,16.98 146,16.64 146,14.98 147.03,13.95 148.11,13.95 R844.1 ; U5.1 113.36,45.93 ; R401.1 R402.1 ; 177.05,79.68 177.11,79.62 179.96,79.62 180.61,78.98 Q7.1 180.61,77.69 180.42,77.5 180.42,75.69 180.69,75.42 R108.2 182.87,76.26 R14.2 ; 177.05,79.68 Q6.1 ; 177.05,79.68 176.77,79.96 175.71,79.96 175.51,80.16 175.51,82.51 v1(175.04,82.98) ; R89.2 174.91,51.95 174.52,51.56 174.52,50.29 ; R134.2 175.88,49.27 176.28,48.87 177.31,48.87 R115.2
  BOTTOM w0.305: 113.36,45.93 113.36,45.94 C14.1 112.01,45.94 111.74,46.21 111.74,47.92 112.02,48.2 112.83,48.2 R64.2 R62.2 114.66,50.39 ; C108.2 182.26,56.8 C97.2 ; v1(165.99,30.51) 167.14,30.51 167.31,30.68 R234.1 ; v1(185,37.06) 184.76,36.82 R169.1 ; v1(183.66,66.02) 183.58,66.11 C110.2 ; U29.1 79.44,74.22 C413.1 ; v1(186.92,31.54) 189.91,34.54 189.91,44.46 v1(189.63,44.74) ; R402.1 v1(52.86,75.74) ; 161.85,63.15 162.51,62.49 Q53.1
  BOTTOM w0.381: R26.2 v1(193.31,41.7) ; v1(76.05,60.85) 76.28,61.08 R441.2 76.71,60.37 R125.1 ; C109.2 179.19,58.23 v1(179.75,57.68) 179.6,57.53 C103.2 C107.2 ; v1(181.31,58.44) 181.37,58.38 C97.2 ; v1(170.19,49.52) 170.42,49.52 170.43,49.51 172.14,49.51 ; v1(188.81,44.71) 188.7,44.82 R573.2 188.71,45.44 R28.2 v1(189.63,44.74) ; C96.2 181.31,63.24 v1(181.31,63.75) ; v1(185.95,86.55) R58.1 R55.2 ; v1(193.31,44.79) R29.2 ; U6.1 78.16,59.91 C21.1 78.73,60.48 v1(78.73,61.02) ; C418.1 R391.1 78.44,68.81 U30.1 ; v1(164.21,26.89) 163.44,26.11 C194.2 161.96,26.97 161.26,26.97 160.63,27.6 160.1,27.6 159.68,28.02 159.68,28.61 159.13,29.17 v1(158.68,29.17) ; v1(186.58,44.64) 186.57,44.65 R138.1 ; R65.2 v1(191.79,41.72) ; R27.2 v1(191.79,44.77) ; C413.1 78.73,74.93 77.31,74.93 76.84,74.46 74.92,74.46 v1(74.89,74.5) 74.14,73.75 74.14,72.8 74.52,72.42 R386.1 74.91,71.76 74.32,71.17 v1(74.32,68.72) ; C111.2 186.96,58.28 v1(186.8,58.44) ; R127.1 167.3,57.07 v1(167.34,57.11) 167.34,59.47 166.87,59.94 166.87,64.9 ; R227.2 v1(188.24,87.52) ; R409.2 66.19,69.65 66.75,69.09 v1(66.75,68.25) ; U32.1 78.16,65.18 R427.1 C420.1 79.52,65.05 80.25,64.32 v1(80.25,62.8) ; R572.2 v1(187.69,44.63)
  BOTTOM w0.508: v2(170.57,65.34) 170.9,65.01 v1(170.9,64.84) ; v1(112.04,49.23) 113.2,50.39 133.28,50.39 136.79,46.87 136.79,42.08 138.73,40.14 148.74,40.14 149.39,40.79 149.39,44.21 ; v1(76.05,60.85) 76.05,60.95 75.48,61.53 74.28,61.53 73.9,61.91 73.9,62.64 R434.2 74.32,63.49 73.52,64.29 73.52,65.34 74.32,66.13 R416.2 R414.2 v1(74.32,68.72) ; v1(158.68,29.17) 156.63,29.17 153.72,26.26 153.72,24.88 151.71,22.86 151.71,21.57 153.17,20.11 153.17,19.39 152.6,18.82 v1(152.09,18.82) ; C418.1 79.52,70.26 80.77,71.5 80.77,73.2 79.73,74.24 C413.1
  BOTTOM w1.016: 159.57,63.15 164.07,63.15 164.63,63.71 165.68,63.71 166.87,64.9 170.12,64.9 v2(170.57,65.34)
  vias: v1(153.91,46.94) v1(154.03,47.57) v2(147.53,44.09) v2(148.29,44.09) v2(154.61,13.62) v2(154.61,12.85) v2(154.61,12.08)
+V1.8A_SPI: length 6.2
  TOP w0.381: 153.81,42.84 R568.2 153.81,41.35 154.41,40.75 155.69,40.75 v1(155.82,40.62)
  BOTTOM w0.203: R40.2 156.27,41.07 v1(155.82,40.62)
  BOTTOM w0.381: v1(156.57,49.23) 156.72,49.07 R41.2
+V1.8S: length 261.3
  TOP w0.178: U11.19 158.84,17.68
  TOP w0.254: 158.84,17.68 v1(158.13,16.97)
  TOP w0.381: v1(189.23,44.09) 188.69,44.09 188.27,44.5 188.27,44.9 187.99,45.19 R22.2 ; C235.2 158.13,16.83 v1(158.13,16.97)
  TOP w0.508: v1(186.31,31.9) 185.82,31.41 D44.P 185.82,30.5 R575.1
  LAY3 w0.381: v1(21.72,43.82) 23.71,43.82 24.73,42.8 24.73,41.61 23.66,40.53 23.66,38.54 24.93,37.26 26.87,37.26 27.66,36.46 27.66,34.72 28.89,33.5 32.44,33.5
  LAY3 w0.406: 32.44,33.5 v2(33.43,32.5) 33.53,32.6 35.03,32.6 39.69,27.94 39.69,25.68 41.26,24.11 48.35,24.11 50,25.75 58.43,25.75 59.53,26.86 63.94,26.86 65.13,25.67 79.85,25.67 85.55,31.37 85.55,34.97 93.63,43.06 100.29,43.06 101.22,42.13 103.95,42.13 104.78,42.97 112.02,42.97 v1(112.85,42.13) 115.96,42.13 116.28,42.45 136.18,42.45 140.52,38.11 v1(140.52,26.32)
  LAY4 w0.305: v1(158.13,16.97) 158.33,16.97 158.68,16.62 158.68,15.53 159.64,14.57 160.51,14.57 160.73,14.34 163.66,14.34 164.25,14.93 165.21,14.93 165.63,14.51 166.64,14.51 168.71,16.58 181.99,16.58 182.61,15.96 v1(186.79,15.96)
  LAY4 w0.406: v1(158.13,16.97) 158.13,16.82 157.62,16.32 154.26,16.32 153.83,15.89 152.34,15.89 151.68,15.23 149.56,15.23 148.4,16.38 148.4,18.8 147.93,19.27 147.93,25.82 147.43,26.32 v1(140.52,26.32)
  BOTTOM w0.203: v1(112.85,42.13) 112.96,42.24 115.12,42.24 115.27,42.39 R72.2
  BOTTOM w0.305: v1(186.79,15.96) 186.79,27.43 187.4,28.03 187.4,30.2 186.31,31.29 v1(186.31,31.9) 186.31,32.35 189.44,35.47 189.44,43.88 v1(189.23,44.09)
  BOTTOM w0.381: FB10.2 v1(21.72,43.82)
  BOTTOM w0.762: R343.2 33.39,32.55 v2(33.43,32.5)
+V1.8U: length 3.4
  TOP w0.178: C233.2 155.92,16.79 156.99,17.87 157.86,17.87 158.04,18.04 U11.17
+V1.15A: length 71.9
  TOP w0.203: U1.AJ35 185.67,66.4
  LAY3 w0.762: v2(150.46,59.5) 153.86,62.9 153.86,70.66 158.3,75.09 v2(158.3,76.37) ; v1(163.07,30.07) 163.07,30.53 v1(163.08,30.54) 165.87,33.33 165.87,41.64 v2(162.41,45.1)
  LAY4 w0.762: 184.29,74.23 183.53,75 174.99,75 v2(173.75,76.23) ; v2(150.46,59.5) 152.13,57.84 152.13,54.76 151.44,54.07 151.44,52.33 157.12,46.65 160.86,46.65 v2(162.41,45.1)
  BOTTOM w0.305: R746.2 165.05,73.39
  vias: v1(186.02,67.54) v1(186.04,66.03) v1(186.58,69.15) v1(186.83,63.8) v1(186.8,59.2)
+V1.15S: length 1.2
  TOP w0.178: 163.58,27.14 163.58,26.95 163.24,26.61 U11.51
+V1.24A: length 62.4
  TOP w0.203: v1(182.88,64.5) 182.5,64.12 U1.AC30 ; v1(175.91,71.31) 175.51,70.92 U1.H44 ; U1.U35 179.37,66.4 v1(179.75,66.78) ; v1(180.53,66.78) 180.15,66.4 U1.V35
  TOP w0.254: v1(180.53,63.75) 180.15,64.12 U1.V30 ; U1.AD38 183.28,68.01 v1(182.9,68.39) ; U1.P38 178.47,68.03 v1(178.83,68.39)
  LAY4 w0.508: v1(178.83,68.39) 179.09,68.39 179.6,68.9 179.6,71.69 178.71,72.58 176.55,72.58 175.91,71.95 v1(175.91,71.31)
  LAY4 w0.762: 165.32,29.41 165.13,29.6 165.13,31.5 162.77,33.87 162.77,39.16 163.53,39.92 165.95,39.92 171.2,45.17 ; 156.73,53.3 156.22,53.3 v1(156.11,53.19) ; 156.73,53.3 163.46,53.3 166.46,50.3 170.48,50.3 170.9,49.87 ; 156.73,53.3 v1(156.61,53.19)
  BOTTOM w0.203: v1(178.83,68.39) 179.07,68.16 C90.2
  BOTTOM w0.381: C95.2 182.8,68.3 v1(182.9,68.39) 183.53,69.03 C83.2 ; v1(181.31,67.54) 181.25,67.6 C79.2 ; v1(181.31,62.23) 181.31,61.59 C84.2 C78.2 ; C86.2 175.75,71.15 v1(175.91,71.31) 175.91,72.2 176.42,72.71 R142.1 ; v1(179.75,66.78) 179.66,66.87 C89.2 R136.1 ; v1(182.88,64.5) 183.04,64.34 C85.2 ; v1(178.83,68.39) 178.82,68.38 R139.1 ; R3107.1 156.05,52.72
  vias: v1(165.85,29.37) v1(165.85,28.84) v1(180.53,67.54) v1(182.88,66.78) v1(183.67,66.78)
+V1P8A_EMMC: length 20.6
  TOP w0.381: v1(180.19,28.44) 179.71,27.96 C144.1
  LAY4 w0.381: v1(186.51,28.48) 186.23,28.48 185.56,29.15 181.15,29.15 180.43,28.44 v1(180.19,28.44)
  BOTTOM w0.203: U8.K6 180,28.62 v1(180.19,28.44) ; U8.Y4 U8.W4 ; U8.Y4 U8.AA3 ; U8.Y4 U8.AA5
  BOTTOM w0.254: U8.AA5 185.52,29.12 186.17,28.48 v1(186.51,28.48)
  BOTTOM w0.305: 186.27,30.66 185.73,30.12 U8.AA3 ; 186.27,30.66 185.61,31.32 185.61,32.22 187.43,34.04 R576.1 ; 186.27,30.66 186.99,29.94 186.99,29.41 186.64,29.06 v1(186.49,29.06)
+V2P8A_EMMC: length 3.1
  BOTTOM w0.203: U8.T10 182.42,26.91 v1(182.42,27.45) 182.44,27.47 182.87,27.47 U8.U9 ; U8.M6 v1(181.4,28.62) 181.4,28.94 U8.N5
+V3.3A: length 452.7
  TOP w0.203: R118.2 76.86,69.54 v1(76.36,70.04)
  TOP w0.254: 164.32,18.29 164.06,18.02 ; 164.32,18.29 v1(164.43,18.29) ; 164.32,18.29 164.29,18.29 ; U11.32 164.29,18.29 ; 164.29,18.29 164.06,18.52
  TOP w0.381: LED2.1 103.78,8.33 103.14,8.97 100.49,8.97 99.44,10.02 99.44,12.4 100.08,13.05 100.08,19.5 101.94,21.35 101.94,24.93 v2(107.7,30.69) ; v1(66.19,68.25) 66.19,68.08 67.42,66.85 v1(67.84,66.85) 69.28,65.41 74.12,65.41 v1(75.3,64.23) ; v1(72.29,69.14) 72.67,69.53 75.65,69.53 76.17,70.04 v1(76.36,70.04)
  TOP w0.508: R172.2 184.22,98.88 v1(183.82,99.28) 183.24,99.85 v1(178.5,99.85) 174.39,99.85 v2(174.02,99.48) ; v1(119.17,57.63) 119.17,58.1 115.18,62.08
  LAY3 w0.254: v1(178.59,85.5) 178.59,94.05 v1(183.82,99.28)
  LAY3 w0.406: v1(170.16,34.83) 168.88,33.55 168.88,28.01 v1(168.88,28)
  LAY3 w0.762: v2(83.45,70.25) 82.76,70.94 77.26,70.94 v1(76.36,70.04) 76.36,69.07 76.56,68.87 76.56,67.37 75.3,66.11 v1(75.3,64.23) 75.3,62.24 75.27,62.21 v1(75.27,60.89) ; 167.03,10.47 167.03,16.32 165.06,18.29 v1(164.43,18.29)
  LAY3 w1.016: v2(107.7,30.69) 113.12,30.69 114.15,29.66 114.15,25.36 115.2,24.3 115.2,22.1 116.92,20.38 133.1,20.38 139.53,13.95 144.69,13.95 147.79,10.86 166.64,10.86 167.03,10.47 187.46,10.47 188.86,11.87 196.53,11.87 199.25,14.59 v2(207.16,14.59) ; v2(112.05,67.35) 110.49,68.91 87.61,68.91 86.27,70.25 v2(83.45,70.25)
  LAY4 w0.305: v1(40.8,75.8) 42.77,77.76 46.51,77.76 47.99,79.25 72.64,79.25 75.8,76.09 v1(75.8,73.78)
  LAY4 w0.508: v1(168.03,75.85) 166.69,77.18 155.45,77.18 154.97,77.67 154.97,78.92 v2(155.57,79.52)
  LAY4 w0.762: v1(75.8,73.78) 76.36,73.22 v1(76.36,70.04)
  BOTTOM w0.178: C419.1 76.27,68.55 76.4,68.43 U30.11 ; U6.11 75.53,60.26 C22.1 ; U32.11 76.53,64.36 75.94,64.96 C421.1
  BOTTOM w0.203: 156.31,47.41 157.85,47.41 158.55,48.12 158.55,56.95 158.6,57 R592.2 ; 156.31,47.41 156.05,47.68 ; 156.31,47.41 156.31,47.41 ; 156.05,47.68 156.05,47.41 ; 156.05,47.68 R3105.1 ; 156.05,47.41 156.31,47.41 ; 156.05,47.41 156.05,47.15 ; 156.05,47.15 156.05,45.43 v1(151.61,40.99) ; 156.05,47.15 156.31,47.41 ; R144.2 R143.2 ; U44.5 168.27,37.11 R554.2 ; v1(168.88,28) 169.13,28 170.83,26.3 171.54,26.3 172.22,25.63 172.22,19.57 168.52,15.88 167.55,15.88 166.29,14.62 165.58,14.62 165.09,15.11 R587.1
  BOTTOM w0.305: v1(178.5,99.85) 178.06,99.41 C113.1 178.06,98.67 U7.5 ; R188.1 v1(116.07,63.25) ; R3109.1 167.86,73.94 168.03,74.11 v1(168.03,75.85) ; C414.1 75.98,73.11 U29.6 ; v1(183.82,99.28) 183.81,99.27 R143.2 ; U27.5 226.48,17.41 C405.1 ; D27.P v1(40.8,75.8)
  BOTTOM w0.381: v1(168.88,28) 168.5,28 168.27,27.77 168.27,23.84 167.2,22.78 166.38,22.78 165.19,21.6 165.19,19.2 164.88,18.88 C238.1 ; R375.2 214.36,13.84 214.96,14.44 215.2,14.44 ; v1(67.84,66.85) 67.33,66.35 D8.P ; R406.1 v1(72.29,69.14) R413.1 ; C421.1 75.3,64.93 v1(75.3,64.23) ; C419.1 76.36,69.52 v1(76.36,70.04) ; v1(75.8,73.78) 75.86,73.71 C414.1 ; v1(178.59,85.5) 178.71,85.39 R123.2 R113.2 ; v2(174.02,99.48) 172.93,99.48 166.29,92.84 166.29,90.96 163.64,88.3 163.64,87.45 163.66,87.42 ; R410.2 v1(66.19,68.25) ; C22.1 v1(75.27,60.89)
  BOTTOM w0.406: v1(164.43,18.29) 164.43,18.87 C238.1
  BOTTOM w0.508: R183.2 v1(119.17,57.63) ; 217.27,17.08 217.95,17.76 C405.1
  BOTTOM w0.762: 163.66,87.42 163.66,87.42 FB38.1 ; v2(83.45,70.25) D30.P
  BOTTOM w1.016: v2(155.57,79.52) 157.34,79.52 161.88,84.06 162.75,84.06 163.66,84.97 163.66,87.42
  vias: v1(155.84,93.13) v1(156.19,92.81) v2(108.46,53.01) v2(109.23,53.01) v2(112.05,66.59) v2(112.81,67.35) v2(112.81,66.59) v2(113.58,67.35) v2(113.58,66.59)
+V3.3A_KBC: length 97.4
  TOP w0.203: v1(45.36,68.5) 45.36,67.39 47.71,65.05 47.71,61.09 48.42,60.38 R456.1 ; v1(62.89,59.8) 62.62,60.07 R445.2
  TOP w0.305: R457.2 D12.P 43.78,81.44 43.34,81 43.34,73.89 v1(44.57,72.65)
  TOP w0.381: v1(61.23,55.91) 62.89,57.57 v1(62.89,59.8) ; v1(59.93,72.95) 60.12,72.76 62.97,72.76 v1(63.23,73.02)
  LAY3 w0.381: v1(63.23,73.02) 63.46,72.78 63.46,60.37 v1(62.89,59.8)
  LAY4 w0.203: v1(62.89,59.8) 64.87,59.8 66.99,61.92 v1(69.04,61.92)
  LAY4 w0.381: v1(47.54,75.73) 47.54,73.6
  BOTTOM w0.178: v1(45.36,68.5) 45.52,68.66 U31.92 ; v1(62.89,59.8) 62.43,60.26 U31.26 ; U31.121 v1(57.53,72.73) ; U31.114 54.73,72.91 v1(54.76,72.95) ; U31.127 v1(59.93,72.95) ; 53.53,55.59 U31.50
  BOTTOM w0.203: v1(47.54,75.73) 47.32,75.51 R828.2 ; R591.1 68.9,61.78 v1(69.04,61.92)
  BOTTOM w0.254: v1(61.23,55.91) 61.23,54.03 59.42,52.22 53.37,52.22 53.02,52.57 53.02,55.08 53.53,55.59
  BOTTOM w0.381: 42.06,69.33 42.06,63.24 41.48,62.65 C416.2 42.7,61.78 FB15.1 ; v1(44.57,72.65) 43.36,71.44 R394.1 R392.1 ; R399.1 v1(55.9,75.74) ; R405.1 56.92,75.57 v1(56.67,75.82) ; R385.1 64.23,73.35 63.56,73.35 v1(63.23,73.02) ; R408.1 v1(57.94,75.74) ; R396.1 v1(54.89,75.74)
  BOTTOM w0.406: R392.1 42.67,69.94 42.06,69.33
  vias: v2(57.35,75.99)
+V3.3A_LDO: length 2.5
  TOP w0.178: U11.54 162.04,27.62 C184.2
+V3.3A_PRIME: length 52.1
  TOP w0.203: U1.D4 174.05,51.44 v1(174.09,51.48) U1.E3 ; U1.B22 172.24,60.27 ; 172.6,60.63 U1.C23
  TOP w0.254: v1(170.71,60.64) 171.09,60.26 172.15,60.26 U1.B22 ; 172.24,60.27 172.6,60.63
  TOP w0.508: R155.2 178.49,26.74 v1(173.59,26.74)
  LAY3 w0.508: v1(176.49,41.19) 176.49,41.36 175.63,42.22 175.63,47.84 176.21,48.42 v1(176.27,48.42)
  LAY4 w0.508: v1(176.27,48.42) 176.22,48.42 174.09,50.56 v1(174.09,51.48) 174.53,51.92 174.53,52.65 172.5,54.68 172.5,58.55 170.71,60.35 v1(170.71,60.64)
  BOTTOM w0.381: v1(170.71,60.64) C102.2 C104.2 ; v1(174.09,51.48) 173.96,51.35 C101.2 ; R133.2 v1(176.27,48.42)
  BOTTOM w0.508: v1(173.59,26.74) 171.54,28.79 171.54,30.57 171.06,31.05 C266.2 ; v1(176.49,41.19) 175.64,41.19 174.77,40.32 174.24,40.32 170.88,36.96 170.88,32.2
+V3.3A_RTC: length 180.5
  TOP w0.203: U1.C5 173.02,52.36 v1(172.86,52.52) 172.8,52.52 U1.B6
  LAY3 w0.406: v1(73.35,72.6) 73.81,73.05 84.13,73.05 84.71,73.63 101.41,73.63 103.22,75.44 116.94,75.44 118.41,76.91 129.92,76.91 132.16,74.67 144.71,74.67 146.02,75.98 v1(150.17,75.98)
  LAY4 w0.381: v1(168.41,58.25) 168.41,55.33 167.43,54.35 167.43,53.79 167.8,53.42 168.79,53.42 169.29,52.92 169.29,51.51 169.69,51.11 v1(170.19,51.11) ; 159.2,58.55 157.96,59.79 157.96,61.6
  LAY4 w0.406: 157.96,61.6 149.63,69.93 149.63,75.43 v1(150.17,75.98) ; v1(73.35,72.6) 73.35,75.67 ; v1(168.41,58.25) 168.11,58.55 159.2,58.55
  LAY4 w0.508: v1(42.22,75.82) 42.24,75.84 46.69,75.84 47.68,76.82 47.68,77.34 48.29,77.95 49.49,77.95 49.93,77.51 56.71,77.51 57.15,77.95 71.07,77.95 73.35,75.67
  BOTTOM w0.203: R83.2 168.66,57.1 168.41,57.36 v1(168.41,58.25) 168.56,58.41 R79.2
  BOTTOM w0.381: v1(73.35,72.6) 73.31,72.64 68.69,72.64 68.09,73.24 66.87,73.24 65.43,71.81 R387.1 ; v1(172.86,52.52) 172.62,52.28 171.35,52.28 170.82,51.75 170.82,51.31 170.62,51.11 v1(170.19,51.11)
  BOTTOM w0.406: C98.2 172.84,52.54 v1(172.86,52.52)
  BOTTOM w0.508: v1(42.22,75.82) 42.22,76.82 41.51,77.53 D27.N C488.2 D26.N
+V3.3A_SW: length 76.3
  TOP w0.203: 164.03,17.44 163.64,17.83 U11.31 ; R558.2 v1(154.95,15.29)
  LAY3 w0.508: v1(174.4,39.63) 174.4,40.02 172.36,42.05 172.36,46.99 171.52,47.84 v1(170.6,47.84)
  LAY4 w0.203: v1(154.95,15.29) 156,14.25 156.77,14.25 157.08,14.56 157.7,14.56 158.77,13.49 158.77,12.98 159.57,12.18 162.77,12.18 164.43,13.84 166.83,13.84 168.57,15.58 170,15.58 v1(170.72,14.86)
  BOTTOM w0.203: v1(154.95,15.29) 152.52,15.29 152.26,15.55 152.26,17.36 152.66,17.76 152.66,18.11 153.48,18.93 R207.2
  BOTTOM w0.381: R140.2 170.97,48.89 170.6,48.52 v1(170.6,47.84) ; 172.81,25.66 173.49,25.66 174.27,26.44 174.27,26.88 172.09,29.06 172.09,31.04 171.49,31.63 171.49,36.72 v1(174.4,39.63)
  BOTTOM w0.508: R231.1 168.44,29.57 170.47,27.54 171.17,27.54 172.81,25.9 172.81,16.47 v1(171.23,14.88)
+V3.3A_WIFI: length 15.8
  BOTTOM w0.305: v1(229.23,11.01) 230.59,12.36 231.99,12.36 233.46,13.84 R789.1 ; Q41.1 236.65,9.75 235.31,9.75 234.11,10.95 230.42,10.95 230.01,10.54 v1(229.21,10.54)
  vias: v1(229.24,28.41)
+V3.3AVCC: length 3.6
  BOTTOM w0.178: U31.74 45.39,61.46 45.31,61.38
  BOTTOM w0.381: C417.1 44.7,60.77 45.31,61.38
  BOTTOM w0.508: C417.1 44.21,60.77 FB15.2
+V3.3S: length 300.5
  TOP w0.305: R253.1 R251.1 134.13,86.39 134.54,86.8 v1(134.68,86.8) ; R586.1 v1(199.64,99.24) ; v2(65.75,61.95) 65.75,61.72 66.08,61.39 71.08,61.39 72.2,60.26 v1(72.21,60.26)
  TOP w0.381: R584.1 126.74,12.98 112.97,12.98 106.61,19.33 106.61,27.62 112.13,33.13 v2(114.45,33.13) ; R574.2 184.29,28.59 185.43,27.45 v1(185.75,27.45) ; U33.5 49.74,65.95 C426.2
  TOP w0.406: C426.2 v1(49.02,65.96)
  TOP w0.762: FB4.1 149.97,88.47 149.97,88.5 v2(149.72,88.75)
  LAY3 w0.508: v1(158.95,85.99) 156.29,88.66 153.55,88.66 153.25,88.96 151.58,88.96 151.36,88.75 v2(149.72,88.75) ; v1(194.68,29.53) 192.6,27.45 v1(185.75,27.45)
  LAY3 w0.762: v2(111.8,44.55) 108.6,47.75 98.33,47.75 94.59,44.02 89.86,44.02 86.44,47.44 82.91,47.44 v2(82.67,47.68)
  LAY3 w1.016: v2(65.75,61.95) 65.75,55.27 66.28,54.73 v2(66.28,50.88) ; v2(66.23,33.16) v2(66.23,47.43)
  LAY4 w0.305: v1(39.15,34.2) 39.15,36.15 v1(37.1,38.2) ; v1(49.02,65.96) 44.13,65.96 41.72,63.54 v1(40.74,63.54)
  BOTTOM w0.203: R537.1 102.82,90.9 103.61,91.7 R536.1 ; U42.5 143.69,87.76 144.75,88.82 R539.1 146.86,89.35 147.16,89.65 149.41,89.65 149.72,89.35 v2(149.72,88.75) 149.72,87.99 149.09,87.36 149.09,86.3 148.21,85.42 R540.1 ; C15.1 112.56,45.01 U5.8
  BOTTOM w0.254: CN11.1 53.96,41.87 53.72,41.63 53.46,41.63 ; R351.1 39.15,34.77 v1(39.15,34.2) R353.1 ; 47.46,41.63 47.46,41.63 CN11.14 ; 47.46,41.63 53.46,41.63 ; 47.46,41.63 46.96,41.63 ; 53.46,41.63 CN11.2 ; 46.96,41.63 45.72,41.63 45.46,41.89 CN11.18 ; 46.96,41.63 46.96,41.63 CN11.15
  BOTTOM w0.305: R70.1 R69.1 112.82,42.78 111.8,43.8 v2(111.8,44.55) 111.8,44.74 112.07,45.01 C15.1 ; U26.5 35.74,37.47 C395.2
  BOTTOM w0.381: v1(128.51,41.77) 127.63,40.89 R305.2 ; R365.1 222.97,25.28 221.11,25.28 220.14,24.31 220.14,20.16 220.66,19.64 224.8,19.64 R364.1 ; 141.94,87.01 U42.5 ; v1(72.21,60.26) 73.23,59.24 R126.2 ; CN11.1 53.96,43.28 54.81,44.13 54.81,45.36 ; 54.81,45.36 55.19,45.74 ; 54.81,45.36 54.81,45.7 ; 54.81,45.36 54.8,45.36 54.42,45.75 ; 37.1,42.11 v1(37.1,38.2) R350.1 36.93,37.48 C395.2 ; R537.1 v1(102.24,88.73)
  BOTTOM w0.406: R146.1 220.59,40.93 221.96,39.56 221.96,36.03 221.11,35.19 ; 221.11,25.28 221.11,35.19 ; 221.11,35.19 220.95,35.02 217.52,35.02 ; FB19.2 89.38,99.88 90.92,98.34
  BOTTOM w0.508: v1(194.68,29.53) 200.06,24.15 200.06,21.68 200.59,21.15 201.04,21.15 207.94,28.05 207.94,34.57 209.82,36.45 ; v1(40.74,63.54) 40.13,62.93 40.13,50.97
  BOTTOM w0.762: v1(158.95,85.99) 159.32,85.99 160.05,86.72 FB6.2
  vias: v1(210.16,40.84) v1(210.17,39.97) v2(92.65,87.37) v2(93.34,98.55) v2(93.41,87.37) v2(94.1,98.55) v2(140.99,86.64) v2(141.75,86.64) v2(163.72,100.68) v2(163.72,99.92) v2(205.2,97.44) v2(205.96,97.44) v2(212.47,103.06) v2(213.23,103.06) v2(216.52,34.94) v2(217.28,34.94) v2(223.81,90.6) v2(223.81,89.84)
+V3.3S_AUDIO: length 25.2
  TOP w0.381: v2(33.12,40.31) 32.5,39.69 30.91,39.69 30,40.6 30,42.13 28.22,43.91 24.01,43.91 22.55,42.45 22.55,40.74 21.22,39.41 v1(19.41,39.41)
  BOTTOM w0.203: 21.47,37.26 21.69,37.04 U25.36
  BOTTOM w0.305: R346.1 32.9,41.59
  BOTTOM w0.381: 21.47,37.26 20.9,37.83 C368.2 20.19,38.67 C367.2 19.74,39.11 19.71,39.11 v1(19.41,39.41)
